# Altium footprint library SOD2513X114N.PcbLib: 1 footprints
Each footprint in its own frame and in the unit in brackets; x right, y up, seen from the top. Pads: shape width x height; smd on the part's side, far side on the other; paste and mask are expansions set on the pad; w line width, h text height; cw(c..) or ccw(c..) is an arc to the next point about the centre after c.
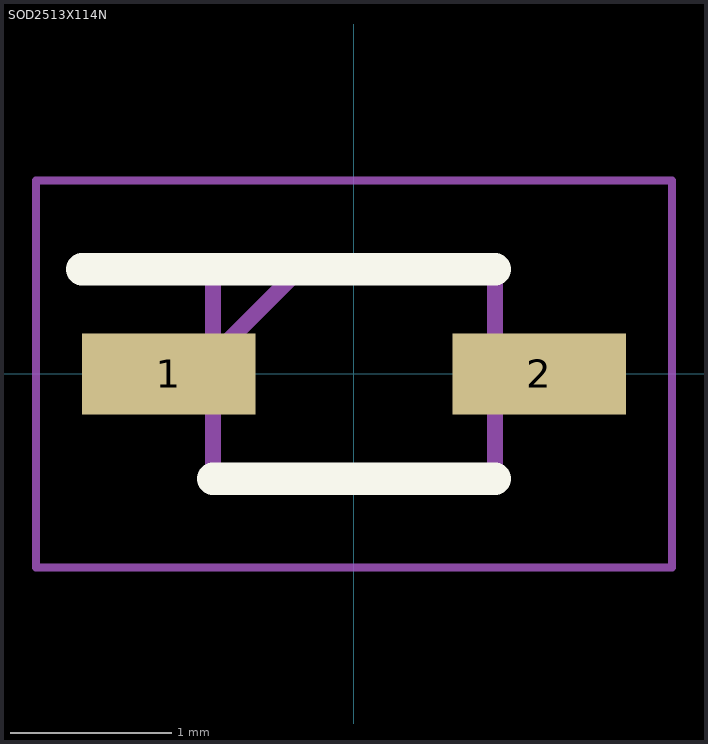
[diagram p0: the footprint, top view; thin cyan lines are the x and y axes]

## SOD2513X114N [mm]
pads (2):
  rect 1.075x0.5 smd: 1(-1.15,0) 2(1.15,0)
Top Overlay:
  lines w0.2: -1.688,0.65 0.875,0.65 ; -0.875,-0.65 0.875,-0.65
Mechanical 15:
  lines w0.1: -0.875,0.112 -0.338,0.65 ; -0.875,-0.65 0.875,-0.65 0.875,0.65 -0.875,0.65 -0.875,-0.65
Mechanical 20:
  lines w0.05: -1.975,-1.2 1.975,-1.2 1.975,1.2 -1.975,1.2 -1.975,-1.2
